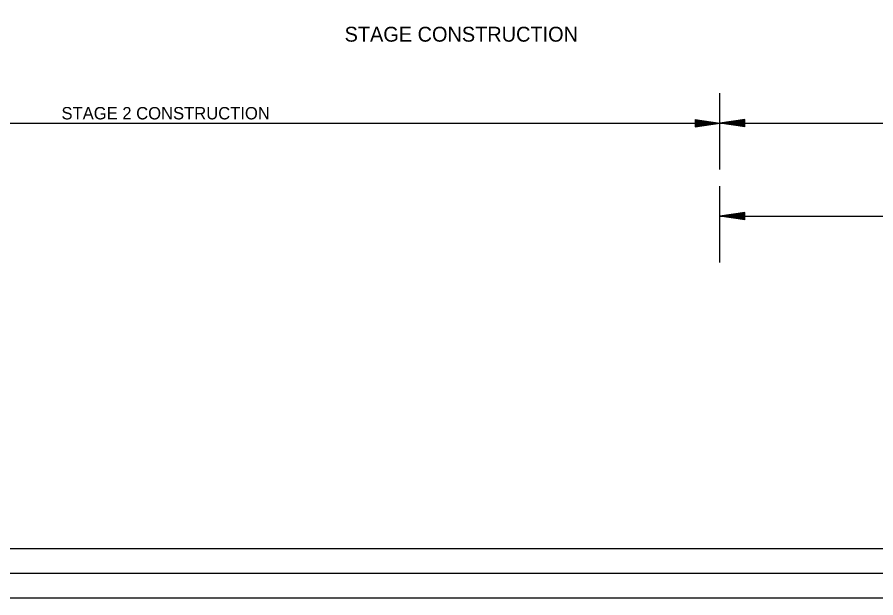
# Model space of a CAD drawing. Extents: x 6125 to 14104, y 8730 to 11067.
# Drawn here: x 8652 to 9345, y 9961 to 10429 of the extents above; entities that cross this region are included whole.
import ezdxf

# ---------------------------------------------------------------- set-up
doc = ezdxf.new("R2010")
doc.units = 0
for name, color, linetype in [('GREEN_TXT', 7, 'Continuous'), ('SEAL-INFO', 7, 'Continuous'), ('Stage 1 Construction', 7, 'Continuous')]:
    doc.layers.add(name, color=color, linetype=linetype)

msp = doc.modelspace()

# ---------------------------------------------------------------- linework, layer by layer
at = {"layer": 'GREEN_TXT'}
for p, q in [((9759.75, 10000), (8178.85, 10000)), ((8022.75, 9960.6), (9782.75, 9960.6))]:
    msp.add_line(p, q, dxfattribs=at)
at = {"layer": 'SEAL-INFO'}
msp.add_lwpolyline([(8116.81, 11046.77), (9783.51, 11046.77), (9783.51, 9980.09), (8116.81, 9980.09)], close=True, dxfattribs=at)
at = {"layer": 'Stage 1 Construction'}
for p, q in [((9218.91, 10305.7), (9218.91, 10367.22)), ((9198.91, 10346.16), (9218.91, 10343.16)), ((9198.91, 10346.16), (9198.91, 10340.16)), ((9238.91, 10346.16), (9218.91, 10343.16)), ((9238.91, 10340.16), (9238.91, 10346.16)), ((8315.6, 10343.16), (9218.91, 10343.16)), ((9198.91, 10345.66), (9215.57, 10343.16)), ((9198.91, 10345.15), (9212.13, 10343.16)), ((9198.91, 10344.65), (9208.8, 10343.16)), ((9198.91, 10344.13), (9205.41, 10343.16)), ((9198.91, 10343.63), (9202.07, 10343.16)), ((9198.91, 10340.16), (9218.91, 10343.16)), ((9198.91, 10342.18), (9205.41, 10343.16)), ((9198.91, 10341.17), (9212.13, 10343.16)), ((9198.91, 10340.66), (9215.57, 10343.16)), ((9198.91, 10341.67), (9208.8, 10343.16)), ((9198.91, 10342.69), (9202.07, 10343.16)), ((9218.91, 10343.16), (9678.01, 10343.16)), ((9238.91, 10340.16), (9218.91, 10343.16)), ((9238.91, 10345.66), (9222.25, 10343.16)), ((9238.91, 10340.66), (9222.25, 10343.16)), ((9238.91, 10345.15), (9225.69, 10343.16)), ((9238.91, 10341.17), (9225.69, 10343.16)), ((9238.91, 10344.65), (9229.02, 10343.16)), ((9238.91, 10341.67), (9229.02, 10343.16)), ((9238.91, 10344.14), (9232.41, 10343.16)), ((9238.91, 10342.19), (9232.41, 10343.16)), ((9238.91, 10343.63), (9235.75, 10343.16)), ((9238.91, 10342.69), (9235.75, 10343.16)), ((9218.91, 10230.73), (9218.91, 10292.25)), ((9238.91, 10271.18), (9218.91, 10268.18)), ((9238.91, 10270.68), (9222.25, 10268.18)), ((9238.91, 10270.17), (9225.69, 10268.18)), ((9238.91, 10265.18), (9238.91, 10271.18)), ((9218.91, 10268.18), (9678.01, 10268.19)), ((9238.91, 10265.18), (9218.91, 10268.18)), ((9238.91, 10265.68), (9222.25, 10268.18)), ((9238.91, 10266.19), (9225.69, 10268.18)), ((9238.91, 10269.67), (9229.02, 10268.18)), ((9238.91, 10266.69), (9229.02, 10268.18)), ((9238.91, 10269.16), (9232.41, 10268.18)), ((9238.91, 10267.21), (9232.41, 10268.18)), ((9238.91, 10268.65), (9235.75, 10268.18)), ((9238.91, 10267.71), (9235.75, 10268.18))]:
    msp.add_line(p, q, dxfattribs=at)

# ---------------------------------------------------------------- texts
for s, height, p in [('STAGE CONSTRUCTION', 12, (8916.37, 10408.83)), ('STAGE 2 CONSTRUCTION', 10, (8688.2, 10346.16))]:
    msp.add_text(s, height=height, dxfattribs=at).set_placement(p)

doc.saveas('drawing.dxf')
